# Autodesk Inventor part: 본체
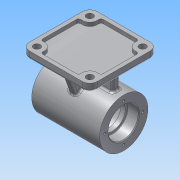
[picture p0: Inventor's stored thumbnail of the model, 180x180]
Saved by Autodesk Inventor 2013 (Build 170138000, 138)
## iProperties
Created: 2019-06
Part Number: 본체
Material: 알루미늄 6061
Document SubType Name: Modeling
Designer: Administrator
Density: 2.71 g/cm^3
Mass: 612.634 g
Surface Area: 622.719 cm^2
Volume: 226.064 cm^3
Author: Administrator
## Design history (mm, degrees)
sketch "스케치1"
  geometry: L1 (-45, 32)-(0, 32); L2 (0, 32)-(0, 0); L3 (0, 0)-(-45, 0); L4 (-45, 0)-(-45, 32); L5 (-45, 20)-(-30, 20); L6 (-30, 20)-(-30, 17); L7 (-30, 17)-(-24, 17); L8 (-24, 17)-(-24, 25); L9 (-24, 25)-(0, 25); 1 further point
  constraints: 18 end point, 4 parallel, 4 perpendicular, 2 point on line, 1 coincident, 1 horizontal
  dimensions: "d0" = 64 diameter of L1 L3; "d2" = 45 distance of L1.start L1.end; "d3" = 40 diameter of L5 L3; "d4" = 34 diameter of L7 L3; "d5" = 50 diameter of L9 L3; "d6" = 15 distance between parallel lines of L6 L4; "d7" = 6 distance of L6.end L7.end
revolve "회전1" sketch "스케치1" stored, may be unused: angle "d8" = 90 deg
sketch "스케치2"
  geometry: L1 (0, 0)-(0, 25); C1 r 20 at (0, 0) reference
  constraints: 2 end point, 1 vertical
  dimensions: "d9" = 25 distance of L1.start L1.end
hole "구멍1" sketch "스케치2" at (0, 25) diameter "d10" = 3.242; stored, may be unused: countersink angle "d14" = 90 deg, drill point angle "d16" = 118 deg; dims "d11" = 7, "d12" = 4, "d13" = 2, "d15" = 9
chamfer "모따기1" distance "d20" = 1; stored, may be unused: second distance "d21" = 2, angle "d22" = 45 deg
fillet "모깎기1" dims "d23" = 0.6
fillet "모깎기2" dims "d24" = 3
sketch "스케치3"
  geometry: 1 further point
node "작업 평면1"
sketch "스케치4"
  geometry: C1 r 5 at (0, 0); 1 further point
  constraints: 1 centre point, 1 coincident
  dimensions: "d26" = 10 diameter of C1
extrude "돌출1" join sketch "스케치4" stored distance "d27" = 10; taper "d28" = 0 deg
sketch "스케치5"
  geometry: C1 r 5 at (0, 0) reference
hole "구멍2" sketch "스케치5" at (0, 0) diameter "d29" = 4.917; stored, may be unused: countersink angle "d33" = 90 deg, drill point angle "d35" = 118 deg; dims "d30" = 30, "d31" = 4, "d32" = 2, "d34" = 30
fillet "모깎기3" dims "d36" = 2
node "작업 평면2"
sketch "스케치6"
  geometry: L1 (-45, -45)-(45, -45); L2 (45, -45)-(45, 45); L3 (45, 45)-(-45, 45); L4 (-45, 45)-(-45, -45); L5 (-45, -45)-(45, 45); L6 (45, -45)-(-45, 45); 1 further point
  constraints: 12 end point, 2 midpoint, 2 parallel, 1 horizontal, 1 perpendicular
  dimensions: "d38" = 90 distance of L3.end L2.end; "d39" = 90 distance of L2.end L1.end
extrude "돌출2" join sketch "스케치6" distance "d40" = 10; taper "d41" = 0 deg
sketch "스케치7"
  geometry: L1 (-35, 5)-(35, 5); L2 (35, 5)-(35, -5); L3 (35, -5)-(-35, -5); L4 (-35, -5)-(-35, 5); 3 further points
  constraints: 8 end point, 2 midpoint, 2 parallel, 1 horizontal, 1 horizontal alignment, 1 perpendicular, 1 vertical alignment
  dimensions: "d42" = 10 distance of L1.end L2.end; "d44" = 70 distance of L1.start L1.end
extrude "돌출3" join sketch "스케치7" stored distance "d45" = 10; taper "d46" = 0 deg
sketch "스케치8"
  geometry: L1 (28.098, 36.038)-(35, 55); L2 (-2.458, -24.879)-(-2.458, -35) reference; L3 (-2.458, -35)-(-5, -35) reference; L4 (-5, -35)-(-5, -33.272) reference; L5 (-5, 31.607)-(-5, 55) reference; L6 (-5, 55)-(-45, 55) reference; L7 (-45, 55)-(-45, 65) reference; L8 (-45, 65)-(45, 65) reference; L9 (45, 65)-(45, 55) reference; L10 (45, 55)-(5, 55) reference; L11 (5, 55)-(5, 31.607) reference; L12 (5, -33.272)-(5, -35) reference; L13 (5, -35)-(2.458, -35) reference; L14 (2.458, -35)-(2.458, -24.879) reference; A1 r 25 centre (0, 0) between (2.458, -24.879) and (-2.458, -24.879) reference; A2 r 32 centre (0, 0) between (-5, 31.607) and (-6.588, -31.314) reference; A3 r 32 centre (0, 0) between (6.588, -31.314) and (5, 31.607) reference; 1 further point
  constraints: 2 end point, 1 point on line, 2 other
  dimensions: "d47" = 10 distance from line of L1.end L9; "d48" = 110 deg angle of L1 L10
feature "리브1" sketch "스케치8" dims "d49" = 1, "d50" = 10, "d51" = 0, "d52" = 0, "d53" = 1, "d54" = 1
fillet "모깎기4" dims "d55" = 3
fillet "모깎기5" dims "d56" = 3
fillet "모깎기6" dims "d57" = 10
sketch "스케치9"
  geometry: C1 r 4.5 at (-35, 35); C2 r 4.5 at (35, 35); A1 r 10 centre (35, 35) between (45, 35) and (35, 45) reference; A2 r 10 centre (-35, 35) between (-35, 45) and (-45, 35) reference; 1 further point
  constraints: 2 centre point, 2 coincident
  dimensions: "d58" = 9 diameter of C1; "d59" = 9 diameter of C2
extrude "돌출4" cut sketch "스케치9" stored distance "d60" = 10; taper "d61" = 0 deg
fillet "모깎기7" dims "d62" = 3
sketch "스케치10"
  geometry: L1 (-26.34, -40)-(26.34, -40); L2 (40, -26.34)-(40, 26.34); L3 (26.34, 40)-(-26.34, 40); L4 (-40, 26.34)-(-40, -26.34); L5 (-40, -40)-(40, 40); L6 (40, -40)-(-40, 40); A1 r 10 centre (-35, -35) between (-45, -35) and (-35, -45) reference; A2 r 10 centre (35, -35) between (35, -45) and (45, -35) reference; A3 r 10 centre (35, 35) between (45, 35) and (35, 45) reference; A4 r 10 centre (-35, 35) between (-35, 45) and (-45, 35) reference; A5 r 10 centre (-35, 35) between (-26.34, 40) and (-40, 26.34); A6 r 10 centre (35, 35) between (26.34, 40) and (40, 26.34); A7 r 10 centre (35, -35) between (40, -26.34) and (26.34, -40); A8 r 10 centre (-35, -35) between (-26.34, -40) and (-40, -26.34); 1 further point
  constraints: 12 end point, 8 point on circle, 4 centre point, 4 coincident, 2 midpoint, 2 parallel, 1 horizontal, 1 perpendicular
  dimensions: "d63" = 80 distance of L5.end L6.end; "d65" = 80 distance of L6.start L5.end; "d66" = 20 diameter of A5; "d67" = 20 diameter of A6; "d68" = 20 diameter of A7; "d69" = 20 diameter of A8
extrude "돌출5" cut sketch "스케치10" distance "d70" = 5; taper "d71" = 0 deg
fillet "모깎기8" dims "d72" = 3
sketch "스케치11"
  geometry: L1 (70, 0)-(0, 0) reference; L2 (-10, 7)-(-10, 0) reference; 2 further points
  constraints: 1 other
  dimensions: "d73" = 45 distance from line of point (35, 4) L2; "d74" = 4 distance from line of L1 point (35, 4)
feature "엠보싱1" sketch "스케치11" dims "d0" = 64, "d2" = 45, "d3" = 40, "d4" = 34, "d5" = 50, "d6" = 15, "d7" = 6, "d75" = 0.5, "d76" = 0
node "솔리드1"
pattern_circular "원형 패턴1" dims angle "d18" = 360 deg
mirror "대칭1"
mirror "대칭2"
mirror "대칭3"
node "절단 모서리 투영1"
other parameters: "d25" = -35, "d37" = 65
